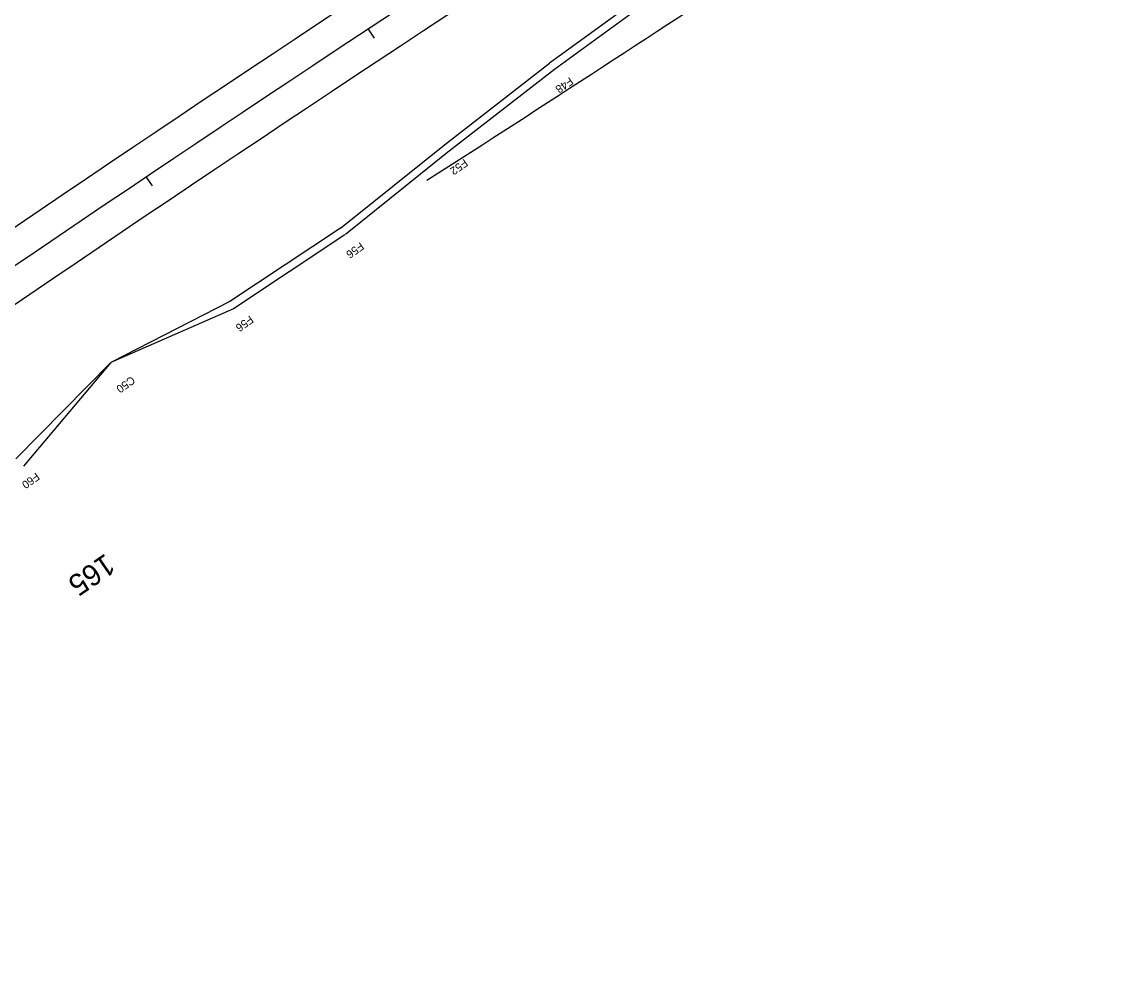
# Model space of a CAD drawing. Extents: x 1469024 to 1473560, y 1105695 to 1109739.
# Drawn here: x 1471479.1 to 1471892.3, y 1107686 to 1108041.8 of the extents above; entities that cross this region are included whole.
import ezdxf

# ---------------------------------------------------------------- set-up
doc = ezdxf.new("R2010")
doc.units = 0
for name, color, linetype in [('RD_HC_CL_Rel', 7, 'Continuous'), ('RD_HC_Data_Tic_Rel', 7, 'Continuous'), ('RD_HC_TX_Rel_Sta50', 7, 'Continuous'), ('RD_PD_CstnLmt', 7, 'Continuous'), ('RD_PD_CstnLmt_TX', 7, 'Continuous'), ('RD_PD_DR_ErosCtrl', 7, 'Continuous'), ('RD_PD_Final_TrvlWay', 7, 'Continuous'), ('RD_PD_RW', 7, 'Continuous')]:
    doc.layers.add(name, color=color, linetype=linetype)

msp = doc.modelspace()

# ---------------------------------------------------------------- linework, layer by layer
at = {"layer": 'RD_HC_CL_Rel'}
msp.add_arc((1477943.58, 1098441.09), 11500, 123.079489, 126.41418, dxfattribs=at)
at = {"layer": 'RD_HC_Data_Tic_Rel'}
for p, q in [((1471608.89, 1108039.09), (1471611.09, 1108035.76)), ((1471525.67, 1107983.65), (1471527.9, 1107980.33))]:
    msp.add_line(p, q, dxfattribs=at)
at = {"layer": 'RD_PD_CstnLmt'}
for p, q in [((1471717.45, 1108055.86), (1471676.93, 1108026.38)), ((1471637.48, 1107995.78), (1471676.93, 1108026.38)), ((1471598.5, 1107964.52), (1471637.48, 1107995.78)), ((1471598.5, 1107964.52), (1471557.04, 1107936.99)), ((1471557.04, 1107936.99), (1471512.43, 1107914.12)), ((1471512.43, 1107914.12), (1471476.8, 1107878.06))]:
    msp.add_line(p, q, dxfattribs=at)
at = {"layer": 'RD_PD_DR_ErosCtrl'}
for p, q in [((1471719.22, 1108053.43), (1471678.7, 1108023.96)), ((1471678.77, 1108024.01), (1471639.31, 1107993.41)), ((1471639.35, 1107993.44), (1471600.37, 1107962.18)), ((1471600.15, 1107962.02), (1471558.41, 1107934.32)), ((1471558.41, 1107934.32), (1471512.43, 1107914.12)), ((1471512.43, 1107914.12), (1471479.64, 1107875.25))]:
    msp.add_line(p, q, dxfattribs=at)
at = {"layer": 'RD_PD_Final_TrvlWay'}
for radius in [11512, 11488]:
    msp.add_arc((1477943.58, 1098441.09), radius, 123.079489, 126.41418, dxfattribs=at)
at = {"layer": 'RD_PD_RW'}
for centre, radius, start, end in [((1465390.13, 1117713.11), 11560, 302.674208, 304.226672), ((1477943.58, 1098441.09), 11625, 123.673947, 126.165068)]:
    msp.add_arc(centre, radius, start, end, dxfattribs=at)

# ---------------------------------------------------------------- texts
at = {"layer": 'RD_HC_TX_Rel_Sta50'}
msp.add_text('165', height=8, rotation=214.4213, dxfattribs=at).set_placement((1471510.4, 1107842.79))
at = {"layer": 'RD_PD_CstnLmt_TX'}
for s, rotation, p in [('F48', 215.1854, (1471684.44, 1108021.28)), ('F52', 215.1854, (1471644.93, 1107990.64)), ('F56', 215.1854, (1471605.97, 1107959.39)), ('F56', 215.4345, (1471564.55, 1107931.9)), ('C50', 215.6836, (1471520.14, 1107909.2)), ('F60', 215.9327, (1471484.34, 1107873.04))]:
    msp.add_text(s, height=3, rotation=rotation, dxfattribs=at).set_placement(p)

doc.saveas('drawing.dxf')
